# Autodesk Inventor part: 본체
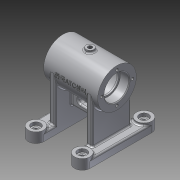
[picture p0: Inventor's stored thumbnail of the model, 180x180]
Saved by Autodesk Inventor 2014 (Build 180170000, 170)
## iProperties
Created: 2015-11
Part Number: 본체
Material: 알루미늄 6061
Document SubType Name: Modeling
Designer: USER
Density: 2.71 g/cm^3
Appearance: 알루미늄 - 평지
Mass: 358.744 g
Surface Area: 459.988 cm^2
Volume: 132.378 cm^3
Author: USER
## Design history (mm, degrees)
sketch "스케치2"
  geometry: L1 (0, 0)-(99.691, 0); L2 (0, 0)-(0, 25); L3 (0, 25)-(70, 25); L4 (70, 25)-(70, 0); L5 (0, 16)-(12, 16); L6 (12, 16)-(12, 14); L7 (12, 14)-(14, 14); L8 (14, 14)-(14, 21); L9 (14, 21)-(56, 21); L10 (56, 21)-(56, 14); L11 (56, 14)-(58, 14); L12 (58, 14)-(58, 16); L13 (58, 16)-(70, 16)
  constraints: 26 end point, 8 perpendicular, 4 parallel, 3 point on line, 1 horizontal
  dimensions: "d0" = 50 diameter of L3 L1; "d1" = 70 distance of L3.end L2.end; "d2" = 32 diameter of L5 L1; "d3" = 12 distance of L5.start L5.end; "d4" = 2 distance of L6.end L7.end; "d5" = 28 diameter of L7 L1; "d6" = 42 diameter of L9 L1; "d7" = 42 distance of L8.end L9.end; "d8" = 2 distance of L10.end L11.end; "d9" = 28 diameter of L11 L1; "d10" = 32 diameter of L13 L1
revolve "회전1" sketch "스케치2" stored, may be unused: angle "d11" = 90 deg
node "작업 평면1"
sketch "스케치3"
  geometry: L1 (5, -40)-(-15, -40); L2 (-15, -40)-(-15, 40); L3 (-15, 40)-(5, 40); L4 (5, 40)-(5, -40); L5 (-55, -40)-(-75, -40); L6 (-75, -40)-(-75, 40); L7 (-75, 40)-(-55, 40); L8 (-55, 40)-(-55, -40); L9 (0, 25)-(-70, 25) reference; L10 (-35, 25)-(-35, -27.416); 3 further points
  constraints: 18 end point, 4 parallel, 3 midpoint, 3 perpendicular, 2 horizontal, 2 horizontal alignment
  dimensions: "d19" = 20 distance of L2.end L3.end; "d20" = 80 distance of L1.end L2.end; "d21" = 20 distance of L6.end L7.end; "d22" = 80 distance of L5.end L6.end; "d24" = 80 distance between parallel lines of L6 L4; "d27" = 40 distance between parallel lines of L4 L10
extrude "돌출1" join sketch "스케치3" distance "d28" = 10; taper "d29" = 0 deg
sketch "스케치4"
  geometry: L1 (-5, -40)-(15, -40) reference; L2 (15, 40)-(-5, 40) reference; L3 (55, -40)-(75, -40) reference; L4 (75, -40)-(75, 40) reference; L5 (75, 40)-(55, 40) reference; L6 (55, 40)-(55, -40) reference; C1 r 10 at (5, 40); C2 r 10 at (65, 40); C3 r 10 at (5, -40); C4 r 10 at (65, -40); 1 further point
  constraints: 4 centre point, 4 midpoint
  dimensions: "d30" = 20 diameter of C1; "d31" = 20 diameter of C2; "d32" = 20 diameter of C3; "d33" = 20 diameter of C4
extrude "돌출2" join sketch "스케치4" distance "d34" = 13; taper "d35" = 0 deg
sketch "스케치6"
  geometry: L1 (10, 80)-(10, 0) reference; L2 (68, 65)-(10, 65); L3 (68, 15)-(10, 15); A1 r 25 centre (68, 40) between (68, 65) and (68, 15) reference; 1 further point
  constraints: 4 end point, 2 perpendicular, 2 point on circle, 2 point on line, 2 tangent
extrude "돌출3" join sketch "스케치6" distance "d36" = 8; taper "d37" = 0 deg
node "작업 평면2"
sketch "스케치7"
  geometry: L1 (75, -68)-(55, -68) reference; L2 (0, -25)-(70, -25) reference; L3 (55, 0)-(55, -58) reference; L4 (15, 0)-(15, -58) reference; L5 (55, -45)-(15, -45); 1 further point
  constraints: 2 end point, 2 point on line, 1 perpendicular
  dimensions: "d38" = 20 distance between parallel lines of L5 L2
feature "리브1" sketch "스케치7" dims "d39" = 1, "d40" = 8, "d41" = 0, "d42" = 0, "d43" = 1, "d44" = 1
node "작업 평면4"
sketch "스케치9"
  geometry: L1 (-70, 25)-(-70, -25) reference; C1 r 5 at (-35, 0); 2 further points
  constraints: 1 centre point, 1 horizontal alignment, 1 midpoint
  dimensions: "d47" = 10 diameter of C1; "d48" = 35 distance from line of C1.centre L1
extrude "돌출4" join sketch "스케치9" stored distance "d49" = 8; taper "d50" = 0 deg
node "작업 평면5"
sketch "스케치11"
  geometry: L1 (0, 0)-(40, 0) reference; L2 (60, -43.322)-(40, -43.322) reference; L3 (-15, 49.678)-(-15, -0.322) reference; L4 (12, -10.322)-(28, -10.322); L5 (12, -13.822)-(28, -13.822); L6 (28, -6.822)-(12, -6.822); A1 r 3.5 centre (12, -10.322) between (12, -6.822) and (12, -13.822); A2 r 3.5 centre (28, -10.322) between (28, -13.822) and (28, -6.822); 2 further points
  constraints: 8 end point, 4 point on circle, 4 tangent, 2 centre point, 2 parallel, 1 midpoint
  dimensions: "d55" = 7 distance of L5.end L6.start; "d56" = 23 dimension on A2 A1; "d57" = 33 distance from line of L2 point (20, -10.322); "d58" = 35 distance from line of point (20, -10.322) L3
extrude "돌출5" cut sketch "스케치11" distance "d59" = 8; taper "d60" = 0 deg
sketch "스케치13"
  geometry: C1 r 10 at (0, 0) reference; C2 r 10 at (0, 80) reference; C3 r 10 at (60, 80) reference; C4 r 10 at (60, 0) reference; 5 further points
  constraints: 4 coincident
hole "구멍1" sketch "스케치13" at (0, 80), (60, 80), (60, 0), (0, 0) diameter "d61" = 6; stored, may be unused: countersink angle "d65" = 90 deg, drill point angle "d67" = 0 deg; dims "d62" = 6, "d63" = 12, "d64" = 4, "d66" = 30
sketch "스케치14"
  geometry: C1 r 16 at (0, 0) reference; 1 further point
  constraints: 1 horizontal alignment
  dimensions: "d68" = 20 distance of C1.centre point (-20, 0)
hole "구멍2" sketch "스케치14" at (-20, 0) diameter "d69" = 3.459; stored, may be unused: countersink angle "d73" = 90 deg, drill point angle "d75" = 118 deg; dims "d70" = 8, "d71" = 12, "d72" = 4, "d74" = 10
node "작업 평면6"
node "작업 평면7"
sketch "스케치15"
  geometry: L1 (0, 0)-(24.249, 14); L2 (-54.163, 0)-(54.163, 0); L3 (24.249, 14)-(21.249, 19.196); L4 (21.249, 19.196)-(18.018, 17.331); A1 r 25 centre (0, 0) between (24.678, 4) and (0, 25) reference; A2 r 25 centre (0, 0) between (21.651, 12.5) and (18.018, 17.331); 2 further points
  constraints: 8 end point, 4 point on circle, 2 coincident, 2 perpendicular, 1 centre point, 1 concentric, 1 horizontal, 1 midpoint, 1 point on line
  dimensions: "d79" = 30 deg angle of L2 L1; "d84" = 6 distance of L1.end L3.end; "d86" = 28 distance from line of point (0, 0) L3
revolve "회전2" sketch "스케치15" stored, may be unused: angle "d87" = 90 deg
sketch "스케치16"
  geometry: C1 r 5 at (0, 0) reference; 2 further points
  constraints: 1 coincident
hole "구멍3" sketch "스케치16" at (0, 0) diameter "d88" = 5.188; stored, may be unused: countersink angle "d92" = 90 deg, drill point angle "d94" = 118 deg; dims "d89" = 15, "d90" = 12, "d91" = 4, "d93" = 15
sketch "스케치17"
  geometry: C1 r 6 at (0, 0) reference; 2 further points
  constraints: 1 coincident
hole "구멍4" sketch "스케치17" at (0, 0) diameter "d95" = 5.188; stored, may be unused: countersink angle "d99" = 90 deg, drill point angle "d101" = 118 deg; dims "d96" = 15, "d97" = 12, "d98" = 4, "d100" = 15
node "작업 평면8"
sketch "스케치18"
  geometry: L1 (35, 25)-(-35, 25) reference; L2 (-35, 25)-(-35, -25) reference; 2 further points
  constraints: 1 other
  dimensions: "d102" = 25 distance from line of L1 point (0, 0); "d103" = 35 distance from line of L2 point (0, 0)
feature "엠보싱1" sketch "스케치18" dims "d104" = 0.5, "d105" = 0
fillet "모깎기1" dims "d106" = 2
fillet "모깎기2" dims "d107" = 2
fillet "모깎기3" dims "d108" = 2
fillet "모깎기4" dims "d109" = 2
fillet "모깎기5" dims "d110" = 2
fillet "모깎기6" dims "d111" = 2
fillet "모깎기7" dims "d112" = 0.3
chamfer "모따기1" distance "d113" = 1; stored, may be unused: second distance "d114" = 2, angle "d115" = 45 deg
chamfer "모따기2" distance "d116" = 1; stored, may be unused: second distance "d117" = 2, angle "d118" = 45 deg
chamfer "모따기3" distance "d119" = 1; stored, may be unused: second distance "d120" = 2, angle "d121" = 45 deg
chamfer "모따기4" distance "d122" = 1; stored, may be unused: second distance "d123" = 2, angle "d124" = 45 deg
fillet "모깎기8" dims "d125" = 3
fillet "모깎기9" dims "d126" = 3
fillet "모깎기10" dims "d127" = 0.3
fillet "모깎기11" dims "d128" = 0.3
chamfer "모따기5" distance "d129" = 1; stored, may be unused: second distance "d130" = 2, angle "d131" = 45 deg
chamfer "모따기6" distance "d132" = 1; stored, may be unused: second distance "d133" = 2, angle "d134" = 45 deg
node "솔리드1"
mirror "대칭1"
pattern_circular "원형 패턴1" dims angle "d77" = 360 deg
mirror "대칭2"
node "투영된 루프1"
other parameters: "d12" = -68, "d46" = 28
